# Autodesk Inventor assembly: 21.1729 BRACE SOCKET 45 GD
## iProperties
Created: 2007-04
Part Number: 21.1729 BRACE SOCKET 45 GD
Document SubType Name: Assembly
Designer: Andy Moles
Author: Andy Moles
